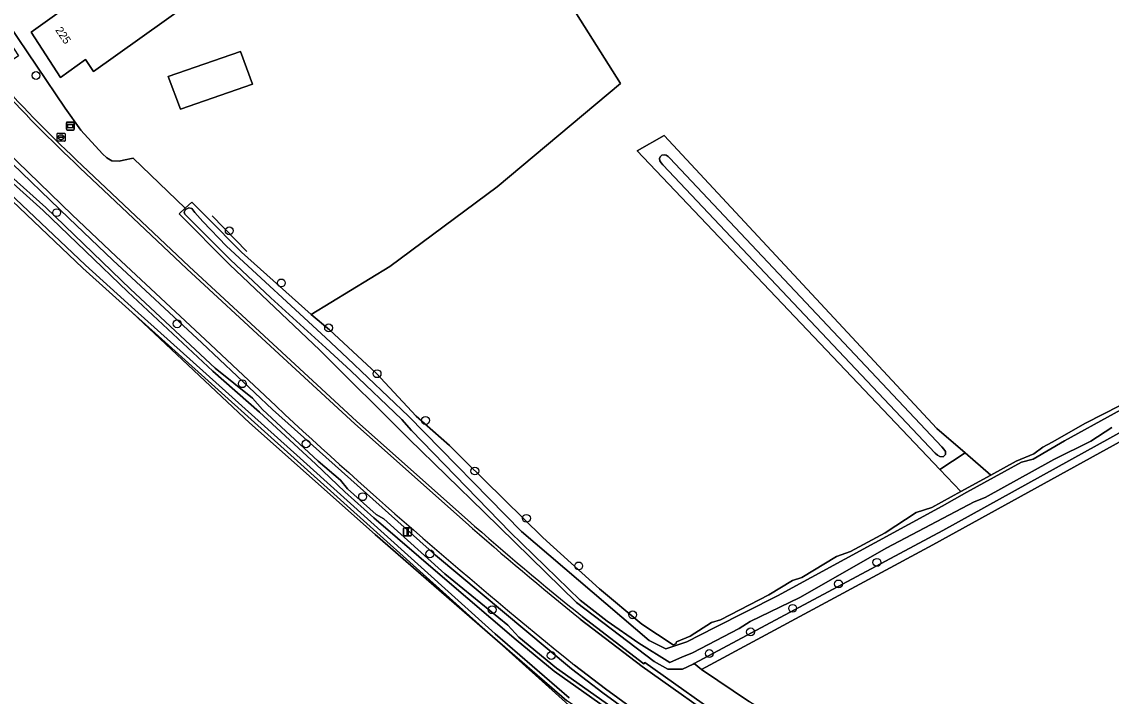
# Model space of a CAD drawing. Extents: x 164494 to 166241, y 382475 to 384495.
# Drawn here: x 165148.9 to 165285, y 382970.6 to 383054.9 of the extents above; entities that cross this region are included whole.
import ezdxf

# ---------------------------------------------------------------- set-up
doc = ezdxf.new("R2010")
doc.units = 0
for name, color, linetype in [('IMGEO_Berm_halfverhard', 7, 'Continuous'), ('IMGEO_Boom', 7, 'Continuous'), ('IMGEO_Bouwland', 7, 'Continuous'), ('IMGEO_Brandkraan', 7, 'Continuous'), ('IMGEO_Erf', 7, 'Continuous'), ('IMGEO_Grasland_agrarisch', 7, 'Continuous'), ('IMGEO_Grasland_overig', 7, 'Continuous'), ('IMGEO_Groenvoorziening', 7, 'Continuous'), ('IMGEO_Hek', 7, 'Continuous'), ('IMGEO_Loofbos', 7, 'Continuous'), ('IMGEO_Oever', 7, 'Continuous'), ('IMGEO_Pand', 7, 'Continuous'), ('IMGEO_Pand_nummerreeks', 7, 'Continuous'), ('IMGEO_Rijbaan_lokaal_gesloten', 7, 'Continuous'), ('IMGEO_Verkeersbordpaal', 7, 'Continuous'), ('IMGEO_Verklikker', 7, 'Continuous'), ('IMGEO_Waterloop', 7, 'Continuous')]:
    doc.layers.add(name, color=color, linetype=linetype)

msp = doc.modelspace()

# ---------------------------------------------------------------- linework, layer by layer
at = {"layer": 'IMGEO_Berm_halfverhard'}
for points in [[(165160.64, 383025.55), (165155.14, 383030.76), (165146.94, 383038.69), (165146.52, 383038.26), (165154.72, 383030.33), (165160.23, 383025.11), (165171.34, 383014.75), (165180.18, 383006.45), (165200.53, 382988.24), (165217.54, 382974.06), (165221.45, 382971.07), (165226.08, 382967.71), (165232.68, 382962.94), (165233.03, 382963.43), (165226.43, 382968.2), (165221.8, 382971.55), (165217.9, 382974.53)], [(165156.13, 383036.64), (165169.5, 383023.99), (165179.93, 383014.36), (165190.47, 383004.65), (165204.3, 382992.37)], [(165204.56, 382992.66), (165190.74, 383004.95), (165169.77, 383024.29), (165156.4, 383036.93)], [(165180.58, 383006.89), (165171.75, 383015.19), (165160.64, 383025.55)], [(165218.64, 382980.28), (165226.36, 382974.35), (165237.4, 382966.51), (165237.73, 382967.01), (165226.71, 382974.84)], [(165226.71, 382974.84), (165226.59, 382974.68), (165218.89, 382980.59)]]:
    msp.add_lwpolyline(points, dxfattribs=at)
for centre, radius, start, end in [((165289.75, 383179.07), 195.3, 222.3904, 226.8272), ((165289.88, 383179.21), 195.09, 222.3938, 226.8277), ((165668.96, 383532.55), 717.52, 227.10588, 231.05086), ((165465.68, 383288.12), 394.7, 228.5297, 231.253), ((165467.01, 383289.7), 396.37, 228.5377, 231.2467)]:
    msp.add_arc(centre, radius, start, end, dxfattribs=at)
at = {"layer": 'IMGEO_Boom'}
for centre in [(165150.64, 383048.15), (165153.22, 383031.03), (165174.78, 383028.76), (165181.29, 383022.25), (165168.27, 383017.15), (165187.19, 383016.64), (165193.25, 383010.91), (165176.41, 383009.66), (165199.3, 383005.08), (165184.38, 383002.16), (165205.47, 382998.76), (165191.44, 382995.55), (165211.91, 382992.86), (165199.84, 382988.41), (165255.7, 382987.35), (165218.43, 382986.91), (165250.9, 382984.66), (165245.18, 382981.62), (165207.63, 382981.44), (165225.18, 382980.81), (165239.91, 382978.67), (165215.01, 382975.72), (165234.76, 382975.97)]:
    msp.add_circle(centre, 0.489, dxfattribs=at)
at = {"layer": 'IMGEO_Bouwland'}
msp.add_lwpolyline([(165218.15, 383055.85), (165223.66, 383047.14), (165208.27, 383034.25), (165194.85, 383024.31), (165185, 383018.32), (165187.31, 383016.39), (165193.14, 383010.99), (165198.12, 383005.63), (165202.28, 383001.96), (165204.27, 383000), (165213.94, 382990.48), (165221.02, 382984.06), (165226.33, 382979.65), (165230.24, 382977.05), (165230.56, 382977.19), (165230.66, 382977.45), (165232.38, 382978.14), (165235.05, 382979.86), (165236.15, 382980.19), (165242.19, 382983.28), (165245.16, 382985.08), (165246.32, 382985.47), (165250.64, 382988.07), (165252.38, 382988.72), (165256.73, 382991.05), (165260.59, 382993.57), (165262.55, 382994.2), (165266.19, 382996.2), (165263.56, 382998.96), (165225.76, 383038.74), (165229.1, 383040.66), (165263.19, 383004.07), (165266.74, 383001.02), (165269.94, 382998.26), (165273.11, 383000), (165275.29, 383000.9), (165276.44, 383001.72), (165277.59, 383002.36), (165281.78, 383004.73), (165292.55, 383010.24)], dxfattribs=at)
at = {"layer": 'IMGEO_Brandkraan'}
for p, q in [((165153.26, 383040.01), (165153.26, 383040.86)), ((165153.34, 383040.94), (165154.19, 383040.94)), ((165153.75, 383040.72), (165153.77, 383040.72)), ((165154.26, 383040.86), (165154.26, 383040.01)), ((165154.19, 383039.94), (165153.34, 383039.94)), ((165153.52, 383040.43), (165153.52, 383040.44)), ((165153.56, 383040.48), (165153.96, 383040.48)), ((165153.96, 383040.39), (165153.56, 383040.39)), ((165153.77, 383040.16), (165153.75, 383040.16)), ((165154, 383040.44), (165154, 383040.43))]:
    msp.add_line(p, q, dxfattribs=at)
for points in [[(165153.26, 383040.01), (165153.26, 383040.86)], [(165153.34, 383040.94), (165154.19, 383040.94)], [(165154.26, 383040.86), (165154.26, 383040.01)], [(165154.19, 383039.94), (165153.34, 383039.94)]]:
    msp.add_lwpolyline(points, dxfattribs=at)
for centre, radius, start, end in [((165153.34, 383040.86), 0.0765, 91.552, 178.448), ((165153.34, 383040.86), 0.0765, 91.552, 178.448), ((165154.19, 383040.86), 0.0765, 1.552, 88.448), ((165154.19, 383040.86), 0.0765, 1.552, 88.448), ((165153.34, 383040.01), 0.0765, 181.552, 268.448), ((165153.34, 383040.01), 0.0765, 181.552, 268.448), ((165153.56, 383040.44), 0.0403, 85.8775, 175.7526), ((165153.56, 383040.43), 0.0366, 178.938, 274.7102), ((165153.97, 383040.44), 0.0386, 1.7309, 96.639), ((165153.96, 383040.44), 0.043, 264.8664, 352.4533), ((165154.19, 383040.01), 0.0765, 271.552, 358.448), ((165154.19, 383040.01), 0.0765, 271.552, 358.448)]:
    msp.add_arc(centre, radius, start, end, dxfattribs=at)
for centre, major_axis, ratio, start_param, end_param in [((165153.75, 383040.44), (-0.387, 0.002), 0.722429, 4.712389, 7.853982), ((165153.77, 383040.44), (-0.39, 0.002), 0.717154, 1.570796, 4.712389)]:
    msp.add_ellipse(centre, major_axis=major_axis, ratio=ratio, start_param=start_param, end_param=end_param, dxfattribs=at)
at = {"layer": 'IMGEO_Erf'}
msp.add_lwpolyline([(165147.19, 383054.58), (165154.26, 383044.06), (165156.24, 383041.34), (165158.94, 383038.39), (165159.48, 383037.85), (165160.12, 383037.5), (165161.03, 383037.44), (165161.58, 383037.57), (165162.78, 383037.82), (165169.28, 383031.59), (165170.09, 383032.35), (165171.96, 383030.47), (165176.32, 383026.1), (165185, 383018.32), (165194.85, 383024.31), (165208.27, 383034.25), (165223.66, 383047.14), (165218.15, 383055.85), (165249.48, 383093.43), (165268.36, 383116.74), (165247.72, 383134.08)], dxfattribs=at)
for points in [[(165175.75, 383061.48), (165157.81, 383048.67), (165156.81, 383050.14), (165153.69, 383047.91), (165150.01, 383053.56), (165170.91, 383068.49)], [(165177.7, 383047.09), (165168.67, 383043.94), (165167.16, 383048.01), (165176.19, 383051.16)]]:
    msp.add_lwpolyline(points, close=True, dxfattribs=at)
at = {"layer": 'IMGEO_Grasland_agrarisch'}
for points in [[(165284.75, 382925.67), (165260.58, 382941.3), (165247.02, 382950.24), (165226.26, 382963.25), (165218.05, 382968.78), (165207.69, 382978.09), (165193.01, 382990.82), (165177.33, 383004.78), (165162.65, 383018.55), (165156.48, 383024.1), (165142.36, 383037.48)], [(165359.73, 382956.18), (165356.23, 382971.7), (165355.68, 382973.4), (165355.57, 382974.98), (165351.45, 382995.91), (165350.65, 383000), (165350.07, 383002.18), (165350.07, 383003.02), (165348.36, 383010.36), (165348.14, 383011.31), (165347.08, 383015.04), (165345.31, 383024.57), (165344.87, 383027.57), (165344.77, 383029.04), (165344.65, 383030.83), (165339.1, 383030.43), (165292.92, 383006.2), (165286.43, 383002.62), (165262.7, 382989.53), (165233.79, 382973.96), (165239.8, 382969.95)]]:
    msp.add_lwpolyline(points, dxfattribs=at)
at = {"layer": 'IMGEO_Grasland_overig'}
for points in [[(165169.28, 383031.59), (165162.78, 383037.82), (165161.58, 383037.57), (165161.03, 383037.44), (165160.12, 383037.5), (165159.48, 383037.85), (165158.94, 383038.39), (165156.24, 383041.34), (165154.26, 383044.06), (165147.19, 383054.58), (165146.29, 383053.95), (165148.43, 383050.62), (165145.68, 383048.76), (165144.92, 383048.31), (165145.51, 383047.41), (165145.8, 383047.68)], [(165156.4, 383036.93), (165169.77, 383024.29), (165190.74, 383004.95), (165204.56, 382992.66)], [(165240.44, 382969.54), (165239.8, 382969.95), (165233.79, 382973.96), (165232.86, 382974.71), (165232.75, 382974.66), (165231.43, 382974.03), (165229.58, 382974.03), (165227.86, 382974.99), (165218.15, 382982.34), (165206.63, 382993.61), (165197.21, 383002.77), (165186.09, 383013.87), (165174.79, 383024.54), (165168.52, 383030.89), (165169.28, 383031.59)], [(165218.89, 382980.59), (165226.59, 382974.68), (165226.71, 382974.84), (165237.73, 382967.01), (165237.4, 382966.51), (165243.48, 382962.53), (165251, 382957.75), (165252.94, 382956.51), (165253.27, 382957.02), (165336.85, 382903.81), (165336.73, 382903.62), (165352.54, 382893.38)]]:
    msp.add_lwpolyline(points, dxfattribs=at)
msp.add_lwpolyline([(165266.74, 383001.02), (165263.56, 382998.96), (165266.19, 382996.2), (165269.94, 382998.26)], close=True, dxfattribs=at)
for centre, radius, start, end in [((165289.88, 383179.21), 195.09, 222.3938, 226.8277), ((165467.01, 383289.7), 396.37, 228.5377, 231.2467)]:
    msp.add_arc(centre, radius, start, end, dxfattribs=at)
at = {"layer": 'IMGEO_Groenvoorziening'}
for points in [[(165143.09, 383039.51), (165151.88, 383031.66), (165162.44, 383021.48), (165173.04, 383011.61), (165177.7, 383007.84), (165178.92, 383006.45), (165185.88, 383000), (165188.7, 382997.6), (165189.56, 382996.52), (165193.12, 382993.32), (165194.09, 382992.81), (165201.73, 382985.91), (165209.58, 382979.51), (165210.95, 382978.02), (165215.68, 382974.13), (165233.49, 382961.57)], [(165226.08, 382967.71), (165221.45, 382971.07), (165217.54, 382974.06), (165200.53, 382988.24), (165180.18, 383006.45), (165171.34, 383014.75), (165160.23, 383025.11), (165154.72, 383030.33), (165146.52, 383038.26)]]:
    msp.add_lwpolyline(points, dxfattribs=at)
for points in [[(165292.92, 383006.2), (165339.1, 383030.43), (165344.65, 383030.83), (165344.1, 383034.39), (165343.43, 383034.01), (165322.32, 383023.55), (165300.9, 383011.79), (165263.93, 382991.34), (165232.86, 382974.71), (165233.79, 382973.96), (165262.7, 382989.53), (165286.43, 383002.62)], [(165162.65, 383018.55), (165177.33, 383004.78), (165193.01, 382990.82), (165207.69, 382978.09), (165183.3, 383000)]]:
    msp.add_lwpolyline(points, close=True, dxfattribs=at)
at = {"layer": 'IMGEO_Hek'}
for points in [[(165176.96, 383026.18), (165172.63, 383030.62)], [(165207.69, 382978.09), (165193.01, 382990.82), (165177.33, 383004.78), (165162.65, 383018.55)], [(165247.02, 382950.24), (165216.96, 382970.05), (165207.69, 382978.09)]]:
    msp.add_lwpolyline(points, dxfattribs=at)
at = {"layer": 'IMGEO_Loofbos'}
msp.add_lwpolyline([(165207.69, 382978.09), (165218.05, 382968.78), (165226.26, 382963.25), (165247.02, 382950.24), (165216.96, 382970.05)], close=True, dxfattribs=at)
at = {"layer": 'IMGEO_Oever'}
for points in [[(165229.1, 383040.66), (165225.76, 383038.74), (165263.56, 382998.96), (165266.74, 383001.02), (165263.19, 383004.07)], [(165263.83, 383001.8), (165264.08, 383001.5), (165264.25, 383001.21), (165264.26, 383000.84), (165264.12, 383000.65), (165263.97, 383000.54), (165263.57, 383000.56), (165263.28, 383000.74), (165262.98, 383000.99), (165228.97, 383037.01), (165228.75, 383037.25), (165228.58, 383037.49), (165228.53, 383037.79), (165228.62, 383038), (165228.84, 383038.2), (165229.12, 383038.25), (165229.36, 383038.2), (165229.62, 383038.02), (165229.83, 383037.81)]]:
    msp.add_lwpolyline(points, close=True, dxfattribs=at)
for points in [[(165233.49, 382961.57), (165215.68, 382974.13), (165210.95, 382978.02), (165209.58, 382979.51), (165201.73, 382985.91), (165194.09, 382992.81), (165193.12, 382993.32), (165189.56, 382996.52), (165188.7, 382997.6), (165185.88, 383000), (165178.92, 383006.45), (165177.7, 383007.84), (165173.04, 383011.61), (165162.44, 383021.48), (165151.88, 383031.66), (165143.09, 383039.51)], [(165217.25, 382970.44), (165208.01, 382978.45), (165183.62, 383000.36), (165162.98, 383018.91), (165156.81, 383024.45), (165142.5, 383038)], [(165142.8, 383039.12), (165151.55, 383031.31), (165162.11, 383021.13), (165172.73, 383011.24), (165178.57, 383006.12), (165185.56, 382999.64), (165189.2, 382996.18), (165192.84, 382992.91), (165201.42, 382985.54), (165210.61, 382977.66), (165215.39, 382973.75), (165233.21, 382961.17)], [(165142.36, 383037.48), (165156.48, 383024.1), (165162.65, 383018.55), (165183.3, 383000), (165207.69, 382978.09), (165216.96, 382970.05)], [(165292.55, 383010.24), (165281.78, 383004.73), (165277.59, 383002.36), (165276.44, 383001.72), (165275.29, 383000.9), (165273.11, 383000), (165269.94, 382998.26), (165266.19, 382996.2), (165262.55, 382994.2), (165260.59, 382993.57), (165256.73, 382991.05), (165252.38, 382988.72), (165250.64, 382988.07), (165246.32, 382985.47), (165245.16, 382985.08), (165242.19, 382983.28), (165236.15, 382980.19), (165235.05, 382979.86), (165232.38, 382978.14), (165230.66, 382977.45), (165230.56, 382977.19), (165230.24, 382977.05), (165226.33, 382979.65), (165221.02, 382984.06), (165213.94, 382990.48), (165204.27, 383000), (165202.28, 383001.96), (165198.12, 383005.63), (165193.14, 383010.99), (165187.31, 383016.39), (165185, 383018.32), (165176.32, 383026.1), (165171.96, 383030.47), (165170.09, 383032.35), (165169.28, 383031.59), (165168.52, 383030.89), (165174.79, 383024.54), (165186.09, 383013.87), (165197.21, 383002.77), (165206.63, 382993.61), (165218.15, 382982.34), (165227.86, 382974.99), (165229.58, 382974.03), (165231.43, 382974.03), (165232.75, 382974.66), (165232.86, 382974.71), (165263.93, 382991.34), (165300.9, 383011.79)], [(165285.05, 383004.19), (165282.42, 383002.5), (165277.79, 383000.18), (165277.44, 383000), (165269.24, 382995.44), (165267.86, 382994.93), (165256.92, 382989.17), (165246.09, 382982.98), (165239.85, 382979.95), (165238.47, 382979.08), (165232.67, 382976.06), (165231.96, 382975.77), (165231.42, 382975.54), (165229.83, 382974.87), (165225.94, 382977.25), (165221.98, 382980.01), (165218.61, 382982.63), (165209.86, 382991.12), (165197.54, 383003.83), (165196.36, 383005.21), (165189.99, 383011.27), (165186.83, 383014.13), (165179.96, 383020.38), (165174.91, 383025.16), (165169.25, 383030.83), (165169.14, 383031.07), (165169.31, 383031.43), (165169.71, 383031.61), (165170.11, 383031.53), (165170.47, 383031.06), (165171.46, 383029.94), (165174.43, 383026.84), (165186.81, 383015.42), (165189.55, 383012.86), (165197.18, 383005.62), (165211.31, 382991.22), (165227.25, 382977.58), (165229.33, 382976.56), (165231.96, 382977.43), (165235.44, 382979.22), (165243.29, 382983.17), (165263.85, 382994.36), (165266.93, 382996.14), (165273.78, 382999.85), (165275.23, 383000.23), (165279.15, 383002.55), (165291.57, 383009.35)]]:
    msp.add_lwpolyline(points, dxfattribs=at)
at = {"layer": 'IMGEO_Pand'}
for points in [[(165153.69, 383047.91), (165156.81, 383050.14), (165157.81, 383048.67), (165175.75, 383061.48), (165170.91, 383068.49), (165150.01, 383053.56)], [(165168.67, 383043.94), (165177.7, 383047.09), (165176.19, 383051.16), (165167.16, 383048.01)]]:
    msp.add_lwpolyline(points, close=True, dxfattribs=at)
at = {"layer": 'IMGEO_Rijbaan_lokaal_gesloten'}
for points in [[(165142.25, 383043.9), (165146.94, 383038.69), (165155.14, 383030.76), (165160.64, 383025.55), (165171.75, 383015.19), (165180.58, 383006.89)], [(165204.3, 382992.37), (165190.47, 383004.65), (165179.93, 383014.36), (165169.5, 383023.99), (165156.13, 383036.64)], [(165226.36, 382974.35), (165218.64, 382980.28)], [(165217.9, 382974.53), (165221.8, 382971.55), (165226.43, 382968.2), (165233.03, 382963.43), (165234.66, 382962.25), (165237.4, 382966.51), (165226.36, 382974.35)]]:
    msp.add_lwpolyline(points, dxfattribs=at)
for centre, radius, start, end in [((165289.75, 383179.07), 195.3, 222.3904, 226.8272), ((165668.96, 383532.55), 717.52, 227.10588, 231.05086), ((165465.68, 383288.12), 394.7, 228.5297, 231.253)]:
    msp.add_arc(centre, radius, start, end, dxfattribs=at)
at = {"layer": 'IMGEO_Verkeersbordpaal'}
for p, q in [((165196.57, 382990.78), (165196.57, 382991.58)), ((165196.57, 382991.58), (165196.57, 382990.78)), ((165196.67, 382991.68), (165197.46, 382991.68)), ((165197.46, 382991.68), (165196.67, 382991.68)), ((165197.56, 382991.58), (165197.56, 382990.78)), ((165197.56, 382990.78), (165197.56, 382991.58)), ((165197.46, 382990.68), (165196.67, 382990.68)), ((165196.67, 382990.68), (165197.46, 382990.68))]:
    msp.add_line(p, q, dxfattribs=at)
msp.add_lwpolyline([(165196.99, 382991.56), (165197.14, 382991.56), (165197.14, 382990.81), (165196.99, 382990.81), (165196.99, 382991.56)], dxfattribs=at)
for centre, start, end in [((165196.67, 382991.58), 90, 180), ((165196.67, 382991.58), 90, 180), ((165197.46, 382991.58), 0, 90), ((165197.46, 382991.58), 360, 90), ((165196.67, 382990.78), 180, 270), ((165196.67, 382990.78), 180, 270), ((165197.46, 382990.78), 270, 0), ((165197.46, 382990.78), 270, 0)]:
    msp.add_arc(centre, 0.1, start, end, dxfattribs=at)
at = {"layer": 'IMGEO_Verklikker'}
for p, q in [((165154.43, 383041.44), (165154.43, 383042.24)), ((165154.43, 383042.24), (165154.43, 383041.44)), ((165154.53, 383042.34), (165155.32, 383042.34)), ((165155.32, 383042.34), (165154.53, 383042.34)), ((165155.42, 383042.24), (165155.42, 383041.44)), ((165155.42, 383041.44), (165155.42, 383042.24)), ((165155.32, 383041.34), (165154.53, 383041.34)), ((165154.53, 383041.34), (165155.32, 383041.34))]:
    msp.add_line(p, q, dxfattribs=at)
for points in [[(165154.53, 383042.07), (165155.32, 383042.07), (165155.32, 383041.61), (165154.53, 383041.61), (165154.53, 383042.07)], [(165154.59, 383042.01), (165154.59, 383041.67), (165155.25, 383041.67), (165155.25, 383042.01), (165154.59, 383042.01)]]:
    msp.add_lwpolyline(points, dxfattribs=at)
for centre, start, end in [((165154.53, 383042.24), 90, 180), ((165154.53, 383042.24), 90, 180), ((165155.32, 383042.24), 0, 90), ((165155.32, 383042.24), 360, 90), ((165154.53, 383041.44), 180, 270), ((165154.53, 383041.44), 180, 270), ((165155.32, 383041.44), 270, 0), ((165155.32, 383041.44), 270, 0)]:
    msp.add_arc(centre, 0.1, start, end, dxfattribs=at)
at = {"layer": 'IMGEO_Waterloop'}
for points in [[(165142.5, 383038), (165156.81, 383024.45), (165162.98, 383018.91), (165183.62, 383000.36), (165208.01, 382978.45), (165217.25, 382970.44)], [(165233.21, 382961.17), (165215.39, 382973.75), (165210.61, 382977.66), (165201.42, 382985.54), (165192.84, 382992.91), (165189.2, 382996.18), (165185.56, 382999.64), (165178.57, 383006.12), (165172.73, 383011.24), (165162.11, 383021.13), (165151.55, 383031.31), (165142.8, 383039.12)], [(165291.57, 383009.35), (165279.15, 383002.55), (165275.23, 383000.23), (165273.78, 382999.85), (165266.93, 382996.14), (165263.85, 382994.36), (165243.29, 382983.17), (165235.44, 382979.22), (165231.96, 382977.43), (165229.33, 382976.56), (165227.25, 382977.58), (165211.31, 382991.22), (165197.18, 383005.62), (165189.55, 383012.86), (165186.81, 383015.42), (165174.43, 383026.84), (165171.46, 383029.94), (165170.47, 383031.06), (165170.11, 383031.53), (165169.71, 383031.61), (165169.31, 383031.43), (165169.14, 383031.07), (165169.25, 383030.83), (165174.91, 383025.16), (165179.96, 383020.38), (165186.83, 383014.13), (165189.99, 383011.27), (165196.36, 383005.21), (165197.54, 383003.83), (165209.86, 382991.12), (165218.61, 382982.63), (165221.98, 382980.01), (165225.94, 382977.25), (165229.83, 382974.87), (165231.42, 382975.54), (165231.96, 382975.77), (165232.67, 382976.06), (165238.47, 382979.08), (165239.85, 382979.95), (165246.09, 382982.98), (165256.92, 382989.17), (165267.86, 382994.93), (165269.24, 382995.44), (165277.44, 383000), (165277.79, 383000.18), (165282.42, 383002.5), (165285.05, 383004.19)]]:
    msp.add_lwpolyline(points, dxfattribs=at)
msp.add_lwpolyline([(165229.83, 383037.81), (165229.62, 383038.02), (165229.36, 383038.2), (165229.12, 383038.25), (165228.84, 383038.2), (165228.62, 383038), (165228.53, 383037.79), (165228.58, 383037.49), (165228.75, 383037.25), (165228.97, 383037.01), (165262.98, 383000.99), (165263.28, 383000.74), (165263.57, 383000.56), (165263.97, 383000.54), (165264.12, 383000.65), (165264.26, 383000.84), (165264.25, 383001.21), (165264.08, 383001.5), (165263.83, 383001.8)], close=True, dxfattribs=at)

# ---------------------------------------------------------------- texts
at = {"layer": 'IMGEO_Pand_nummerreeks'}
msp.add_text('225', height=1, rotation=304.4242, dxfattribs=at).set_placement((165153, 383053.81))

doc.saveas('drawing.dxf')
